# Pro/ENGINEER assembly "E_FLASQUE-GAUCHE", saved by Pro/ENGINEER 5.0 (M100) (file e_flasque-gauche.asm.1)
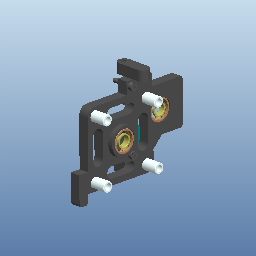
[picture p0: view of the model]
Units: millimeter Newton Second (mmNs); MM, TONNE, HOURS

Other components: 1-FLASQUE_GAUCHE1, ROULEMENT-BC_10X22X6, ROULEMENT-BC_10X22X6, ROULEMENT-BC_10X22X6, VIS_CHC_M-4X20, VIS_CHC_M-4X20, 12-PLAQUE_FREIN-B

Other named items: A-DROITE, A-DESSUS, A-FACE, A-R0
